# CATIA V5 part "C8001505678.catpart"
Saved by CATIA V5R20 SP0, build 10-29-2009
Part number: C8001505678
Source: Unknown
Property "A": "70"
Property "ARTICLENO": "C8001505678"
Property "B": "32"
Property "BOMINFO": "C8001505678"
Property "C": "120"
Property "CA": "C8001505678"
Property "D1": "120"
Property "DES": "ROTATING EYEBOLT WITH RING Ton 15 M56x78"
Property "E": "130"
Property "H": "280"
Property "L": "78"
Property "LINA": "C8001505678"
Property "NB": "C8001505678"
Property "NBSYN": "$CODE."
Property "NN": "C800"
Property "NT": "Rotating eyebolt with ring"
Property "SIZE": "M56"
Property "SUPPLIER": "CF"
Property "SW": "95"
Property "WEIGHT": "10000"
Property "WLL": "15.00"
Bounding box of the stored display mesh (mm): x -67 to 67, y -78 to 311.813, z -60 to 60
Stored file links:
  C:\Users\Utente\Desktop\3D files 800\C8001505678.catpart
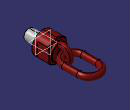
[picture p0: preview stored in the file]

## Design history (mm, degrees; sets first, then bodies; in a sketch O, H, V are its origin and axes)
Body1 "Geometry.1" (main body)
  Solid1 "C8001505678.catpart": solid without history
